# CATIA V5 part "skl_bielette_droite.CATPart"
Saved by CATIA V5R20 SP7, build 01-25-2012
Part number: skl_bielette_droite
Publications: "Axe_pivot_biellette_droite_bras_droit", "Axe_pivot_bielette_droite_levier", "Plan.1"
Bounding box of the stored display mesh (mm): x 68.75 to 200, y 627.38 to 700, z 0 to 20
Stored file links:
  U:\IAO\thinkmotion catia2\skl_bielette_droite.CATPart
  U:\IAO\thinkmotion catia2\skl_862_adubourgno.CATProduct
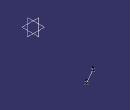
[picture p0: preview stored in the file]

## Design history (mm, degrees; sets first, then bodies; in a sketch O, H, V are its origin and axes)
Set1
  Point1 "B": linked copy from another document
  Point2 "F": linked copy from another document
  Plane1: linked copy from another document
Set2
  Line1: type PtPt, FirstPoint Point1, SecondPoint Point2
  Line2 "Axe_pivot_bielette_droite_levier": type Normal, RefPoint Point1, RefSkin Plane1, Start 0, End 20
  Line3 "Axe_pivot_biellette_droite_bras_droit": type Normal, RefPoint Point2, RefSkin Plane1, Start 0, End 20
Body1 (main body)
